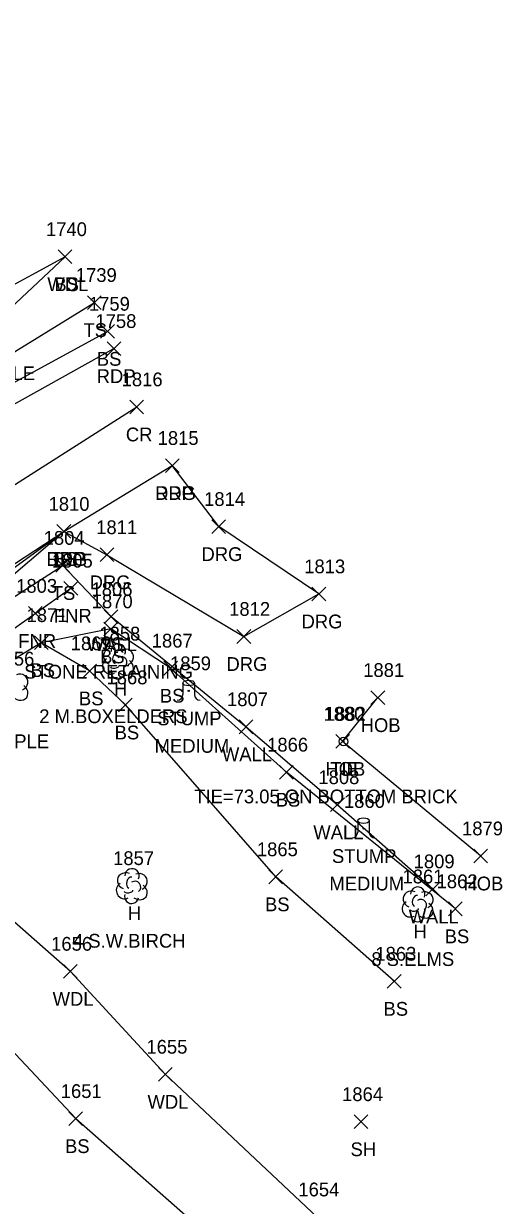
# Model space of a CAD drawing. Extents: x 1647133 to 1649138, y 411736 to 414924.
# Drawn here: x 1649068.5 to 1649138, y 412180 to 412351.7 of the extents above; entities that cross this region are included whole.
import ezdxf

# ---------------------------------------------------------------- set-up
doc = ezdxf.new("R2010")
doc.units = 0
for name, color, linetype in [('C_A', 7, 'Continuous'), ('C_C', 7, 'Continuous'), ('C_I', 7, 'Continuous'), ('CBP', 7, 'Continuous'), ('L_A', 7, 'Continuous'), ('L_C', 7, 'Continuous'), ('L_I', 7, 'Continuous'), ('L_TIC', 7, 'Continuous'), ('LAWA', 7, 'Continuous'), ('LBC', 7, 'Continuous'), ('LELB', 7, 'Continuous'), ('LFNC', 7, 'Continuous'), ('LTD', 7, 'Continuous'), ('LTS', 7, 'Continuous'), ('LW', 7, 'Continuous'), ('P_A', 7, 'Continuous'), ('P_I', 7, 'Continuous'), ('P_TIC', 7, 'Continuous'), ('PET', 7, 'Continuous'), ('PRC', 7, 'Continuous'), ('R_A', 7, 'Continuous'), ('R_I', 7, 'Continuous'), ('R_TIC', 7, 'Continuous'), ('RDG', 7, 'Continuous')]:
    doc.layers.add(name, color=color, linetype=linetype)

msp = doc.modelspace()

# ---------------------------------------------------------------- linework, layer by layer
at = {"layer": 'CBP'}
for radius in [0.625, 0.0833]:
    msp.add_circle((1649114.92, 412247.4), radius, dxfattribs=at)
at = {"layer": 'L_TIC'}
for points in [[(1649073.48, 412316.81), (1649075.48, 412318.81)], [(1649075.48, 412316.81), (1649073.48, 412318.81)], [(1649073.48, 412316.81), (1649075.48, 412318.81)], [(1649075.48, 412316.81), (1649073.48, 412318.81)], [(1649077.74, 412310.15), (1649079.74, 412312.15)], [(1649079.74, 412310.15), (1649077.74, 412312.15)], [(1649079.64, 412305.97), (1649081.64, 412307.97)], [(1649081.64, 412305.97), (1649079.64, 412307.97)], [(1649073.29, 412276.9), (1649075.29, 412278.9)], [(1649075.29, 412276.9), (1649073.29, 412278.9)], [(1649073.29, 412276.9), (1649075.29, 412278.9)], [(1649075.29, 412276.9), (1649073.29, 412278.9)], [(1649073.14, 412271.96), (1649075.14, 412273.96)], [(1649075.14, 412271.96), (1649073.14, 412273.96)], [(1649074.32, 412268.65), (1649076.32, 412270.65)], [(1649076.32, 412268.65), (1649074.32, 412270.65)], [(1649069.14, 412264.99), (1649071.14, 412266.99)], [(1649071.14, 412264.99), (1649069.14, 412266.99)], [(1649080.15, 412264.52), (1649082.15, 412266.52)], [(1649082.15, 412264.52), (1649080.15, 412266.52)], [(1649080.15, 412264.52), (1649082.15, 412266.52)], [(1649082.15, 412264.52), (1649080.15, 412266.52)], [(1649080.13, 412262.74), (1649082.13, 412264.74)], [(1649082.13, 412262.74), (1649080.13, 412264.74)], [(1649070.01, 412260.74), (1649072.01, 412262.74)], [(1649072.01, 412260.74), (1649070.01, 412262.74)], [(1649070.01, 412260.74), (1649072.01, 412262.74)], [(1649072.01, 412260.74), (1649070.01, 412262.74)], [(1649077.05, 412256.64), (1649079.05, 412258.64)], [(1649079.05, 412256.64), (1649077.05, 412258.64)], [(1649088.81, 412257.03), (1649090.81, 412259.03)], [(1649090.81, 412257.03), (1649088.81, 412259.03)], [(1649118.93, 412252.76), (1649120.93, 412254.76)], [(1649120.93, 412252.76), (1649118.93, 412254.76)], [(1649082.24, 412251.69), (1649084.24, 412253.69)], [(1649084.24, 412251.69), (1649082.24, 412253.69)], [(1649099.78, 412248.52), (1649101.78, 412250.52)], [(1649101.78, 412248.52), (1649099.78, 412250.52)], [(1649113.8, 412246.4), (1649115.8, 412248.4)], [(1649115.8, 412246.4), (1649113.8, 412248.4)], [(1649105.64, 412241.92), (1649107.64, 412243.92)], [(1649107.64, 412241.92), (1649105.64, 412243.92)], [(1649113.06, 412237.19), (1649115.06, 412239.19)], [(1649115.06, 412237.19), (1649113.06, 412239.19)], [(1649133.86, 412229.75), (1649135.86, 412231.75)], [(1649135.86, 412229.75), (1649133.86, 412231.75)], [(1649104.09, 412226.72), (1649106.09, 412228.72)], [(1649106.09, 412226.72), (1649104.09, 412228.72)], [(1649126.91, 412224.96), (1649128.91, 412226.96)], [(1649128.91, 412224.96), (1649126.91, 412226.96)], [(1649130.2, 412222.07), (1649132.2, 412224.07)], [(1649132.2, 412222.07), (1649130.2, 412224.07)], [(1649074.25, 412212.99), (1649076.25, 412214.99)], [(1649076.25, 412212.99), (1649074.25, 412214.99)], [(1649121.3, 412211.54), (1649123.3, 412213.54)], [(1649123.3, 412211.54), (1649121.3, 412213.54)], [(1649088.04, 412198.03), (1649090.04, 412200.03)], [(1649090.04, 412198.03), (1649088.04, 412200.03)], [(1649075.03, 412191.59), (1649077.03, 412193.59)], [(1649077.03, 412191.59), (1649075.03, 412193.59)], [(1649116.47, 412191.14), (1649118.47, 412193.14)], [(1649118.47, 412191.14), (1649116.47, 412193.14)]]:
    msp.add_lwpolyline(points, dxfattribs=at)
at = {"layer": 'LAWA'}
for points in [[(1648980.94, 412375.36), (1648998.78, 412351.65), (1648999.91, 412349.91), (1649016.43, 412330.17), (1649036.65, 412309.86), (1649048.18, 412303.54), (1649061.81, 412305.92), (1649074.48, 412317.81)], [(1649111.12, 412178.3), (1649089.04, 412199.03), (1649075.25, 412213.99), (1649058.93, 412228.31), (1649052.09, 412230.86), (1649036.04, 412232.41), (1649032.16, 412233.29), (1649023.71, 412232.35), (1649011.83, 412226.16), (1649003.25, 412219.94), (1648994.7, 412211.05)]]:
    msp.add_lwpolyline(points, dxfattribs=at)
at = {"layer": 'LBC'}
msp.add_lwpolyline([(1649134.86, 412230.75), (1649114.8, 412247.4), (1649119.93, 412253.76)], dxfattribs=at)
at = {"layer": 'LELB'}
for points in [[(1648977.8, 412371.73), (1648995.49, 412346.49), (1649012.44, 412327.29), (1649033.13, 412307.09), (1649042.05, 412298.88), (1649049.01, 412296), (1649063.94, 412302.06), (1649078.74, 412311.15)], [(1648975.88, 412370.36), (1648993.7, 412345.02), (1649009.48, 412324.93), (1649024.13, 412306.01), (1649038.07, 412295.6), (1649044.47, 412292.74), (1649053.23, 412292.05), (1649080.64, 412306.97)], [(1649074.48, 412317.81), (1649064.12, 412312.16), (1649054.35, 412313.81), (1649051.38, 412320.13), (1649055.42, 412338.12)], [(1649020.44, 412234.74), (1649037.68, 412251.43), (1649059.13, 412266.88), (1649074.29, 412277.9)], [(1649020.44, 412234.74), (1649039, 412249.99), (1649059.6, 412265.41), (1649074.29, 412277.9)], [(1649028.32, 412239.29), (1649039.67, 412248.16), (1649060.24, 412264.03), (1649074.14, 412272.96), (1649081.15, 412265.52)], [(1649131.2, 412223.07), (1649106.64, 412242.92), (1649089.81, 412258.03), (1649081.13, 412263.74), (1649071.01, 412261.74), (1649058.32, 412254.04), (1649048.33, 412245.04), (1649036.7, 412236.9)], [(1649122.3, 412212.54), (1649105.09, 412227.72), (1649083.24, 412252.69), (1649078.05, 412257.64), (1649071.01, 412261.74)], [(1649076.64, 412139.6), (1649064.07, 412155.76), (1649043.7, 412175.56), (1649025.51, 412201.61), (1649004.57, 412203.92), (1649026.54, 412214.26), (1649035.27, 412210.48), (1649038.43, 412209.72), (1649056.28, 412213.62), (1649076.03, 412192.59), (1649101.78, 412169.94)]]:
    msp.add_lwpolyline(points, dxfattribs=at)
at = {"layer": 'LFNC'}
msp.add_lwpolyline([(1649034.49, 412240.31), (1649042.96, 412246.39), (1649058.78, 412257.97), (1649070.14, 412265.99), (1649075.32, 412269.65)], dxfattribs=at)
at = {"layer": 'LTD'}
for p, q in [((1649082.15, 412259.05), (1649082.15, 412259.05)), ((1649082.15, 412259.05), (1649082.15, 412259.05)), ((1649084.15, 412226.43), (1649084.15, 412226.43)), ((1649084.15, 412226.43), (1649084.15, 412226.43)), ((1649125.69, 412223.77), (1649125.69, 412223.77)), ((1649125.69, 412223.77), (1649125.69, 412223.77))]:
    msp.add_line(p, q, dxfattribs=at)
for centre in [(1649082.2, 412260.49), (1649084.2, 412227.86), (1649125.73, 412225.21)]:
    msp.add_arc(centre, 1.05, 335.5272, 180.9563, dxfattribs=at)
for centre, major_axis, ratio, start_param, end_param in [((1649081.36, 412259.72), (1.21, -0.51), 0.895232, 1.570796, 4.712389), ((1649083.19, 412259.64), (-1.14, -0.48), 0.949671, 1.570796, 4.712389), ((1649081.07, 412258.35), (0.58, -1.04), 0.959034, 3.141593, 6.283185), ((1649081.94, 412259.51), (-0.208, -0.792), 0.645439, 3.141593, 6.283185), ((1649082.65, 412258.89), (-0.5, 0.667), 0.989748, 3.141593, 6.283185), ((1649083.15, 412258.22), (-1.09, 0.79), 0.841452, 1.570796, 4.712389), ((1649082.15, 412257.55), (0.26, 1.06), 0.942809, 1.570796, 4.712389), ((1649081.69, 412258.3), (-0.625, -0.083), 0.423636, 0, 3.141593), ((1649067.85, 412255.99), (-1.14, -0.48), 0.949671, 1.570796, 4.712389), ((1649067.81, 412254.58), (-1.09, 0.79), 0.841452, 1.570796, 4.712389), ((1649083.36, 412227.1), (1.21, -0.51), 0.895232, 1.570796, 4.712389), ((1649085.2, 412227.01), (-1.14, -0.48), 0.949671, 1.570796, 4.712389), ((1649083.07, 412225.72), (0.58, -1.04), 0.959034, 3.141593, 6.283185), ((1649083.95, 412226.89), (-0.208, -0.792), 0.645439, 3.141593, 6.283185), ((1649084.65, 412226.26), (-0.5, 0.667), 0.989748, 3.141593, 6.283185), ((1649085.15, 412225.6), (-1.09, 0.79), 0.841452, 1.570796, 4.712389), ((1649084.15, 412224.93), (0.26, 1.06), 0.942809, 1.570796, 4.712389), ((1649083.7, 412225.68), (-0.625, -0.083), 0.423636, 0, 3.141593), ((1649124.9, 412224.44), (1.21, -0.51), 0.895232, 1.570796, 4.712389), ((1649125.48, 412224.23), (-0.208, -0.792), 0.645439, 3.141593, 6.283185), ((1649126.73, 412224.36), (-1.14, -0.48), 0.949671, 1.570796, 4.712389), ((1649124.6, 412223.06), (0.58, -1.04), 0.959034, 3.141593, 6.283185), ((1649125.23, 412223.02), (-0.625, -0.083), 0.423636, 0, 3.141593), ((1649126.19, 412223.61), (-0.5, 0.667), 0.989748, 3.141593, 6.283185), ((1649126.69, 412222.94), (-1.09, 0.79), 0.841452, 1.570796, 4.712389), ((1649125.69, 412222.27), (0.26, 1.06), 0.942809, 1.570796, 4.712389)]:
    msp.add_ellipse(centre, major_axis=major_axis, ratio=ratio, start_param=start_param, end_param=end_param, dxfattribs=at)
at = {"layer": 'LTS'}
for p, q in [((1649091.6, 412255.88), (1649091.6, 412254.22)), ((1649093.27, 412255.72), (1649093.27, 412255.88)), ((1649093.27, 412255.88), (1649093.27, 412254.22)), ((1649092.44, 412254.74), (1649092.44, 412254.74)), ((1649092.44, 412254.74), (1649092.44, 412254.74)), ((1649092.44, 412254.72), (1649092.44, 412254.72)), ((1649117, 412235.88), (1649117, 412234.22)), ((1649118.67, 412235.72), (1649118.67, 412235.88)), ((1649118.67, 412235.88), (1649118.67, 412234.22)), ((1649117.84, 412234.74), (1649117.84, 412234.74)), ((1649117.84, 412234.74), (1649117.84, 412234.74)), ((1649117.84, 412234.72), (1649117.84, 412234.72))]:
    msp.add_line(p, q, dxfattribs=at)
for centre in [(1649092.44, 412254.74), (1649117.84, 412234.74)]:
    msp.add_circle(centre, 0.0833, dxfattribs=at)
for centre, start, end in [((1649090.77, 412254.22), 270, 360), ((1649094.1, 412254.22), 180, 270), ((1649116.17, 412234.22), 270, 360), ((1649119.5, 412234.22), 180, 270)]:
    msp.add_arc(centre, 0.833, start, end, dxfattribs=at)
for centre in [(1649092.44, 412255.88), (1649117.84, 412235.88)]:
    msp.add_ellipse(centre, major_axis=(-0.833, 0), ratio=0.5, dxfattribs=at)
at = {"layer": 'LW'}
msp.add_lwpolyline([(1649081.15, 412265.52), (1649100.78, 412249.52), (1649114.06, 412238.19), (1649127.91, 412225.96)], dxfattribs=at)
at = {"layer": 'P_TIC'}
for points in [[(1649080.58, 412303.46), (1649082.58, 412305.46)], [(1649082.58, 412303.46), (1649080.58, 412305.46)], [(1649083.88, 412294.99), (1649085.88, 412296.99)], [(1649085.88, 412294.99), (1649083.88, 412296.99)], [(1649089.06, 412286.47), (1649091.06, 412288.47)], [(1649091.06, 412286.47), (1649089.06, 412288.47)], [(1649073.29, 412276.9), (1649075.29, 412278.9)], [(1649075.29, 412276.9), (1649073.29, 412278.9)]]:
    msp.add_lwpolyline(points, dxfattribs=at)
at = {"layer": 'PET'}
for points in [[(1648998.77, 412333.42), (1648994.31, 412324.57), (1648993.83, 412315.07), (1649000.69, 412300.56), (1649003.42, 412288.2), (1649004.9, 412270.19), (1649001.61, 412254.48), (1648993.91, 412243.99), (1648984.63, 412233.46), (1648979.62, 412228.92), (1648985.33, 412222.55), (1648990.49, 412216.93), (1649002.33, 412227.19), (1649016.43, 412237.44), (1649036.67, 412252.92), (1649058.78, 412267.78), (1649074.29, 412277.9), (1649090.06, 412287.47)], [(1648998.77, 412333.42), (1649006.6, 412323.57), (1649021.41, 412303.61), (1649034.73, 412292.12), (1649046.68, 412286.42), (1649056.64, 412290.6), (1649081.58, 412304.46)]]:
    msp.add_lwpolyline(points, dxfattribs=at)
at = {"layer": 'PRC'}
msp.add_lwpolyline([(1648985.33, 412222.55), (1648998.03, 412233.46), (1649011.26, 412245.34), (1649030.66, 412261.2), (1649052.94, 412275.66), (1649084.88, 412295.99)], dxfattribs=at)
at = {"layer": 'R_TIC'}
for points in [[(1649089.06, 412286.47), (1649091.06, 412288.47)], [(1649091.06, 412286.47), (1649089.06, 412288.47)], [(1649073.29, 412276.9), (1649075.29, 412278.9)], [(1649075.29, 412276.9), (1649073.29, 412278.9)], [(1649095.81, 412277.6), (1649097.81, 412279.6)], [(1649097.81, 412277.6), (1649095.81, 412279.6)], [(1649079.56, 412273.51), (1649081.56, 412275.51)], [(1649081.56, 412273.51), (1649079.56, 412275.51)], [(1649110.35, 412267.82), (1649112.35, 412269.82)], [(1649112.35, 412267.82), (1649110.35, 412269.82)], [(1649099.45, 412261.64), (1649101.45, 412263.64)], [(1649101.45, 412261.64), (1649099.45, 412263.64)]]:
    msp.add_lwpolyline(points, dxfattribs=at)
at = {"layer": 'RDG'}
msp.add_lwpolyline([(1649074.29, 412277.9), (1649080.56, 412274.51), (1649100.45, 412262.64), (1649111.35, 412268.82), (1649096.81, 412278.6), (1649090.06, 412287.47)], dxfattribs=at)

# ---------------------------------------------------------------- texts
at = {"layer": 'C_A'}
msp.add_text('TIE', height=2, dxfattribs=at).set_placement((1649113, 412242.4))
at = {"layer": 'C_C'}
msp.add_text('TIE=73.05 ON BOTTOM BRICK', height=2, dxfattribs=at).set_placement((1649093.25, 412238.4))
at = {"layer": 'C_I'}
msp.add_text('1882', height=2, dxfattribs=at).set_placement((1649112.23, 412250.4))
at = {"layer": 'L_A'}
for s, p in [('WDL', (1649071.9, 412312.81)), ('BS', (1649072.92, 412312.81)), ('TS', (1649077.15, 412306.15)), ('BS', (1649079.09, 412301.97)), ('BS', (1649072.74, 412272.9)), ('BS', (1649072.74, 412272.9)), ('TS', (1649072.55, 412267.96)), ('FNR', (1649072.85, 412264.65)), ('FNR', (1649067.67, 412260.99)), ('TS', (1649079.55, 412260.52)), ('WALL', (1649077.63, 412260.52)), ('BS', (1649079.57, 412258.74)), ('BS', (1649069.45, 412256.74)), ('BS', (1649069.45, 412256.74)), ('H', (1649081.59, 412254.05)), ('BS', (1649076.49, 412252.64)), ('BS', (1649088.25, 412253.03)), ('STUMP', (1649087.86, 412249.74)), ('HOB', (1649117.43, 412248.76)), ('BS', (1649081.68, 412247.69)), ('WALL', (1649097.27, 412244.52)), ('HOB', (1649112.3, 412242.4)), ('BS', (1649105.08, 412237.92)), ('WALL', (1649110.55, 412233.19)), ('STUMP', (1649113.26, 412229.74)), ('HOB', (1649132.36, 412225.75)), ('H', (1649083.59, 412221.43)), ('BS', (1649103.53, 412222.72)), ('WALL', (1649124.4, 412220.96)), ('H', (1649125.12, 412218.77)), ('BS', (1649129.64, 412218.07)), ('WDL', (1649072.67, 412208.99)), ('BS', (1649120.75, 412207.54)), ('WDL', (1649086.46, 412194.03)), ('BS', (1649074.47, 412187.59)), ('SH', (1649115.96, 412187.14))]:
    msp.add_text(s, height=2, dxfattribs=at).set_placement(p)
at = {"layer": 'L_C'}
for s, p in [('STONE & CONCRETE RUBBLE', (1649031.17, 412299.89)), ('STONE & CONCRETE RUBBLE', (1649031.17, 412299.89)), ('STONE RETAINING', (1649068.54, 412256.52)), ('2 M.BOXELDERS', (1649070.72, 412250.05)), ('S.APPLE', (1649061, 412246.41)), ('MEDIUM', (1649087.49, 412245.74)), ('MEDIUM', (1649112.89, 412225.74)), ('4 S.W.BIRCH', (1649075.63, 412217.43)), ('8 S.ELMS', (1649118.98, 412214.77))]:
    msp.add_text(s, height=2, dxfattribs=at).set_placement(p)
at = {"layer": 'L_I'}
for s, p in [('1740', (1649071.7, 412320.81)), ('1740', (1649071.7, 412320.81)), ('1739', (1649076.04, 412314.15)), ('1759', (1649077.94, 412309.97)), ('1810', (1649072.08, 412280.9)), ('1810', (1649072.08, 412280.9)), ('1804', (1649071.37, 412275.96)), ('1805', (1649072.55, 412272.65)), ('1803', (1649067.37, 412268.99)), ('1806', (1649078.32, 412268.52)), ('1806', (1649078.32, 412268.52)), ('1870', (1649078.35, 412266.74)), ('1871', (1649068.88, 412264.74)), ('1871', (1649068.88, 412264.74)), ('1869', (1649075.3, 412260.64)), ('1858', (1649079.46, 412262.05)), ('1867', (1649087.07, 412261.03)), ('1856', (1649064.06, 412258.41)), ('1859', (1649089.73, 412257.74)), ('1868', (1649080.5, 412255.69)), ('1881', (1649117.8, 412256.76)), ('1807', (1649098.01, 412252.52)), ('1880', (1649112.02, 412250.4)), ('1866', (1649103.84, 412245.92)), ('1808', (1649111.29, 412241.19)), ('1860', (1649115, 412237.74)), ('1879', (1649132.16, 412233.75)), ('1865', (1649102.35, 412230.72)), ('1857', (1649081.46, 412229.43)), ('1809', (1649125.13, 412228.96)), ('1861', (1649123.51, 412226.77)), ('1862', (1649128.46, 412226.07)), ('1656', (1649072.45, 412216.99)), ('1863', (1649119.56, 412215.54)), ('1655', (1649086.3, 412202.03)), ('1651', (1649073.85, 412195.59)), ('1864', (1649114.73, 412195.14)), ('1654', (1649108.38, 412181.3))]:
    msp.add_text(s, height=2, dxfattribs=at).set_placement(p)
at = {"layer": 'P_A'}
for s, p in [('RDP', (1649079.07, 412299.46)), ('CR', (1649083.31, 412290.99)), ('RDP', (1649087.55, 412282.47)), ('RDP', (1649071.78, 412272.9))]:
    msp.add_text(s, height=2, dxfattribs=at).set_placement(p)
at = {"layer": 'P_I'}
for s, p in [('1758', (1649078.89, 412307.46)), ('1816', (1649082.7, 412298.99)), ('1815', (1649087.93, 412290.47)), ('1810', (1649072.08, 412280.9))]:
    msp.add_text(s, height=2, dxfattribs=at).set_placement(p)
at = {"layer": 'R_A'}
for p in [(1649087.55, 412282.47), (1649071.78, 412272.9), (1649094.3, 412273.6), (1649078.05, 412269.51), (1649108.84, 412263.82), (1649097.93, 412257.64)]:
    msp.add_text('DRG', height=2, dxfattribs=at).set_placement(p)
at = {"layer": 'R_I'}
for s, p in [('1815', (1649087.93, 412290.47)), ('1814', (1649094.68, 412281.6)), ('1810', (1649072.08, 412280.9)), ('1811', (1649079, 412277.51)), ('1813', (1649109.23, 412271.82)), ('1812', (1649098.32, 412265.64))]:
    msp.add_text(s, height=2, dxfattribs=at).set_placement(p)

doc.saveas('drawing.dxf')
